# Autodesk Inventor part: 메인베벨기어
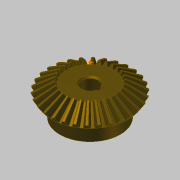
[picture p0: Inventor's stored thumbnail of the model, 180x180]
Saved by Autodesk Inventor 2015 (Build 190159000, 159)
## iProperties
Created: 2018-09
Part Number: 메인베벨기어
Material: 강철, 탄소
Document SubType Name: Modeling
Categories: <?xml version="1.0" encoding="UTF-16"?> <MemberInstance><Categories><FamilyTemplate><FamilyTemplateParameter ValueType="xs:double" Id="1" ObjectReferenceKey="da
Mass: 290.333 g
Surface Area: 107.709 cm^2
Volume: 36.8911 cm^3
Density: 7.87 g/cm^3
Appearance: 얼룩무늬
CustomPartVersion: 1
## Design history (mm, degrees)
node "맨 위 점"
node "메쉬 평면2"
sketch "톱니 본체 스케치"
  geometry: L1 (0, 0)-(28.669, -21.997); L2 (28.669, -21.997)-(31.109, -18.336); L3 (31.109, -18.336)-(0, 0); L4 (30, -20)-(0, 0); L5 (17.219, -13.212)-(18.685, -11.013); L6 (28.669, -21.997)-(17.219, -13.212); L7 (31.109, -18.336)-(18.685, -11.013); L8 (0, -39.387)-(0, 6.564) reference; L9 (0, -20)-(31.109, -20)
  constraints: 16 end point, 4 point on line, 3 perpendicular, 2 collinear, 1 horizontal alignment, 1 vertical alignment
  dimensions: "d0" = 60 diameter of L4.start L8 (= da_de); "d1" = 57.33744 diameter of L1.end L8 (= da_dfe); "d2" = 62.2188 diameter of L2.end L8 (= da_dae); "d3" = 14.4 distance between parallel lines of L2 L5 (= da_b); "d4" = 18.3359 vertical distance of L2.end L1.start (= da_ve)
revolve "톱니 본체" sketch "톱니 본체 스케치" stored, may be unused: angle "d5" = 90 deg
node "시작점"
node "톱니 평면"
sketch "시작 스케치"
  geometry: L1 (0, -23.505)-(0, 10.645) reference; L2 (-0.709, -2.928)-(0.709, -2.928); A1 r 19.188 centre (-19.457, -7.014) between (-0.709, -2.928) and (-3.232, 3.229); A2 r 19.188 centre (19.457, -7.014) between (3.232, 3.229) and (0.709, -2.928); A3 r 57.403 centre (0, -54.083) between (3.232, 3.229) and (-3.232, 3.229); 1 further point
  constraints: 6 point on circle, 3 centre point, 3 symmetric about line, 2 end point, 1 coincident, 1 perpendicular, 1 other
  dimensions: "d7" = 19.18795 radius of A1 (= fd_rr); "d8" = 19.45712 horizontal distance of point (0, -54.083) A1.centre (= fd_x); "d9" = 47.06905 vertical distance of point (0, -54.083) A1.centre (= fd_y); "d57" = 57.40327 radius of A3 (= 0.5 x fd_dva + 0.3 x da_he); "d58" = 51.15527 distance from line of A3.centre L2 (= 0.5 x fd_dva - 1.12 x da_he)
node "끝점"
  node "끝 평면"
sketch "3D 스케치 오른쪽"
  node "Helical Curve Right" dims "d65" = 229.90621 (computed from da_dm, da_delta, da_beta), "d66" = 31.5, "d67" = 60 (= da_de), "d68" = -9.82794 (= -da_delta), "d69" = 8.10972 (computed from fd_loft, da_delta)
node "끝 평면 오른쪽"
sketch "끝 스케치 오른쪽"
  geometry: L1 (0, -41.54)-(0, 13.178) reference; L2 (-0.422, -1.69)-(0.422, -1.69); A1 r 11.427 centre (-11.587, -4.123) between (-0.422, -1.69) and (-1.925, 1.977); A2 r 11.427 centre (11.587, -4.123) between (1.925, 1.977) and (0.422, -1.69); A3 r 34.184 centre (0, -32.153) between (1.925, 1.977) and (-1.925, 1.977); 1 further point
  constraints: 6 point on circle, 3 centre point, 3 symmetric about line, 2 end point, 1 coincident, 1 perpendicular, 1 other
  dimensions: "d70" = 11.58699 horizontal distance of A3.centre A1.centre (computed from fd_x, fd_ratio); "d71" = 28.03028 vertical distance of point (0, -32.153) A1.centre (computed from fd_y, fd_ratio); "d72" = 11.4267 radius of A1 (computed from fd_rr, fd_ratio); "d73" = 30.46369 distance from line of point (0, -32.153) L2 (computed from d58, fd_ratio); "d74" = 34.18446 radius of A3 (computed from d57, fd_ratio)
feature "로프트 오른쪽" sketch "끝 스케치 오른쪽" dims "d75" = 0, "d77" = 0, "d79" = 0, "d80" = 90 deg, "d85" = 20, "d92" = 90 deg, "d93" = 90 deg, "da_teethtype" = 0 [user parameter]
sketch "3D 스케치 왼쪽"
  node "Helical Curve Left" dims "d26" = 229.90621 (computed from da_dm, da_delta, da_beta), "d27" = 8.10972 (computed from fd_loft, da_delta), "d28" = 60 (= da_de), "d29" = -9.82794 (= -da_delta)
node "끝 평면 왼쪽"
sketch "끝 스케치 왼쪽" dims "d56" = 10.3728 (derived)
  geometry: L1 (0, -43.753)-(0, 15.405) reference; L2 (-0.422, -1.678)-(0.422, -1.678); A1 r 11.427 centre (-11.587, -4.111) between (-0.422, -1.678) and (-1.925, 1.988); A2 r 11.427 centre (11.587, -4.111) between (1.925, 1.988) and (0.422, -1.678); A3 r 34.184 centre (0, -32.142) between (1.925, 1.988) and (-1.925, 1.988); 2 further points; 1 other entity
  constraints: 6 point on circle, 3 centre point, 3 symmetric about line, 2 end point, 1 coincident, 2 other
  dimensions: "d30" = 11.4267 radius of A1 (computed from fd_rr, fd_ratio); "d31" = 11.58699 horizontal distance of point (0, -32.142) A1.centre (computed from fd_x, fd_ratio); "d32" = 28.03028 vertical distance of A1.centre point (0, -32.142) (computed from fd_y, fd_ratio); "d61" = 34.18446 radius of A3 (computed from d57, fd_ratio); "d62" = 30.46369 distance from line of point (0, -32.142) L2 (computed from d58, fd_ratio)
feature "로프트 왼쪽" sketch "끝 스케치 왼쪽" dims "d35" = 0, "d37" = 0, "d39" = 0, "d40" = 90 deg, "d84" = 10, "d90" = 90 deg, "d91" = 90 deg, "da_teethtype" = 0 [user parameter]
sketch "본체 스케치"
  geometry: L1 (0, -35.038)-(0, -19.531) reference; L2 (28.669, -21.997)-(17.219, -13.212) reference; L3 (17.219, -13.212)-(0, -13.212); L4 (28.669, -21.997)-(0, -21.997)
  constraints: 4 end point, 2 perpendicular, 2 point on line
revolve "본체 고정" sketch "본체 스케치" stored, may be unused: angle "d46" = 90 deg
feature "피치 지름" dims angle "d47" = 90 deg
sketch "스케치8"
  geometry: C1 r 22.5 at (0, 0); 1 further point
  constraints: 1 centre point, 1 coincident
  dimensions: "d94" = 45 diameter of C1
extrude "돌출1" join sketch "스케치8" distance "d95" = 13; taper "d96" = 0 deg
sketch "스케치9"
  geometry: 1 further point
hole "구멍1" sketch "스케치9" at (0, 0) diameter "d97" = 12; stored, may be unused: countersink angle "d101" = 90 deg, drill point angle "d103" = 118 deg; dims "d98" = 6, "d99" = 4, "d100" = 2, "d102" = 8
sketch "스케치10"
  geometry: L1 (5.657, 2)-(7.8, 2); L2 (7.8, 2)-(7.8, -2); L3 (7.8, -2)-(5.657, -2); A1 r 6 centre (0, 0) between (5.657, 2) and (5.657, -2) reference; 1 further point
  constraints: 6 end point, 2 parallel, 2 point on circle, 1 horizontal, 1 perpendicular
  dimensions: "d104" = 4 distance of L1.end L2.end; "d112" = 13.8 dimension on A1 L2
extrude "돌출2" cut sketch "스케치10" stored distance "d106" = 10; taper "d107" = 0 deg
chamfer "모따기1" distance "d108" = 1; stored, may be unused: second distance "d109" = 2, angle "d110" = 45 deg
fillet "모깎기1" dims "d111" = 2
body "Solid1"
feature "로프트" dims "d17" = 0, "d18" = 90 deg, "d19" = 0, "d20" = 90 deg, "d89" = 0, "da_teethtype" = 0 [user parameter]
pattern_circular "원형 패턴" dims angle "d22" = 360 deg, "d88" = 0, "da_teethtype" = 0 [user parameter]
pattern_circular "원형 패턴 오른쪽" dims angle "d82" = 360 deg, "da_teethtype" = 0 [user parameter]
pattern_circular "원형 패턴 왼쪽" dims angle "d42" = 360 deg, "da_teethtype" = 0 [user parameter]
sketch "끝 스케치"
  geometry: L1 (0, -15.359)-(0, 6.983) reference; L2 (-0.422, -1.69)-(0.422, -1.69); A1 r 11.427 centre (-11.587, -4.123) between (-0.422, -1.69) and (-1.925, 1.977); A2 r 11.427 centre (11.587, -4.123) between (1.925, 1.977) and (0.422, -1.69); A3 r 34.184 centre (0, -32.153) between (1.925, 1.977) and (-1.925, 1.977); 1 further point
  constraints: 6 point on circle, 3 centre point, 3 symmetric about line, 2 end point, 1 coincident, 1 other
  dimensions: "d12" = 11.4267 radius of A1 (computed from fd_rr, fd_ratio); "d15" = 11.58699 horizontal distance of A1.centre point (0, -32.153) (computed from fd_x, fd_ratio); "d16" = 28.03028 vertical distance of A1.centre point (0, -32.153) (computed from fd_y, fd_ratio); "d59" = 34.18446 radius of A3 (computed from d57, fd_ratio); "d60" = 30.46369 distance from line of A3.centre L2 (computed from d58, fd_ratio)
sketch "Sketch6"
  geometry: L1 (30, -20)-(0, 0) reference; L2 (0, -37.8)-(0, 6.3) reference
body "Srf1"
other parameters: "da_b" = 14.4 [user parameter; used in 2 equation terms], "da_de" = 60 [user parameter; used in 4 equation terms], "da_dae" = 62.2188 [user parameter; used in 2 equation terms], "da_dfe" = 57.33744 [user parameter; used in 1 equation term], "da_le" = 36.05551 [user parameter; used in 1 equation term], "da_omega" = 90 deg [user parameter; used in 1 equation term], "da_beta" = 0 [user parameter; used in 2 equation terms], "da_delta" = 9.82794 [user parameter; used in 8 equation terms], "da_alpha" = 20 deg [user parameter; used in 2 equation terms], "da_he" = 4.4 [user parameter; used in 4 equation terms], "da_ve" = 18.3359 [user parameter; used in 1 equation term], "fd_dv" = 108.16654 (computed from da_de, da_delta) [user parameter; used in 1 equation term], "fd_dva" = 112.16654 (computed from da_dae, da_delta) [user parameter; used in 3 equation terms], "fd_dvb" = 101.6433 (computed from fd_dv, da_alpha) [user parameter; used in 2 equation terms], "da_zv" = 540.83269 [user parameter; used in 1 equation term], "fd_loft" = 14.62 (= da_b + 0.05 x da_he) [user parameter; used in 4 equation terms], "fd_ratio" = 5.95514 (computed from da_le, fd_loft) [user parameter; used in 15 equation terms], "fd_rr" = 19.18795 (computed from fd_dd, fd_dvb) [user parameter; used in 6 equation terms], "fd_angle" = 0.29367 (computed from da_zv) [user parameter; used in 4 equation terms], "fd_x1" = 1.58802 (computed from da_dvw, fd_angle) [user parameter; used in 1 equation term], "fd_y1" = 54.05995 (computed from da_dvw, fd_angle) [user parameter; used in 1 equation term], "fd_x2" = 17.8691 (computed from fd_rr, fd_angle2, fd_angle) [user parameter; used in 1 equation term], "fd_y2" = 6.9909 (computed from fd_rr, fd_angle2, fd_angle) [user parameter; used in 1 equation term], "fd_x" = 19.45712 (= fd_x1 + fd_x2) [user parameter; used in 4 equation terms], "fd_y" = 47.06905 (= fd_y1 - fd_y2) [user parameter; used in 4 equation terms], "fd_angle2" = 3.43555 (computed from fd_dvb, fd_dd, da_alpha) [user parameter; used in 2 equation terms], "fd_dd" = 108.64654 (= fd_dva - 0.8 x da_he) [user parameter; used in 2 equation terms], "da_dvw" = 108.16654 [user parameter; used in 2 equation terms], "d11" = 14.62 (= fd_loft), "da_dm" = 48.01848 [user parameter; used in 2 equation terms], "da_x" = 0 [user parameter], "da_m" = 2 [user parameter], "d48" = 0, "d49" = 0, "d50" = 90 deg (= da_omega), "d51" = 6 deg (computed from da_z), "d52" = 0, "d53" = 0, "d54" = 0
